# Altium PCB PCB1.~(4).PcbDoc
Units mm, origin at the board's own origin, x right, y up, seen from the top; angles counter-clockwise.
Board outline 152.4 x 101.6 mm, 2 copper layers (Top Layer, Bottom Layer); 2 components, 2 nets, 16 pads, 0 vias.
Unrouted connection lines stored in the file: 1.
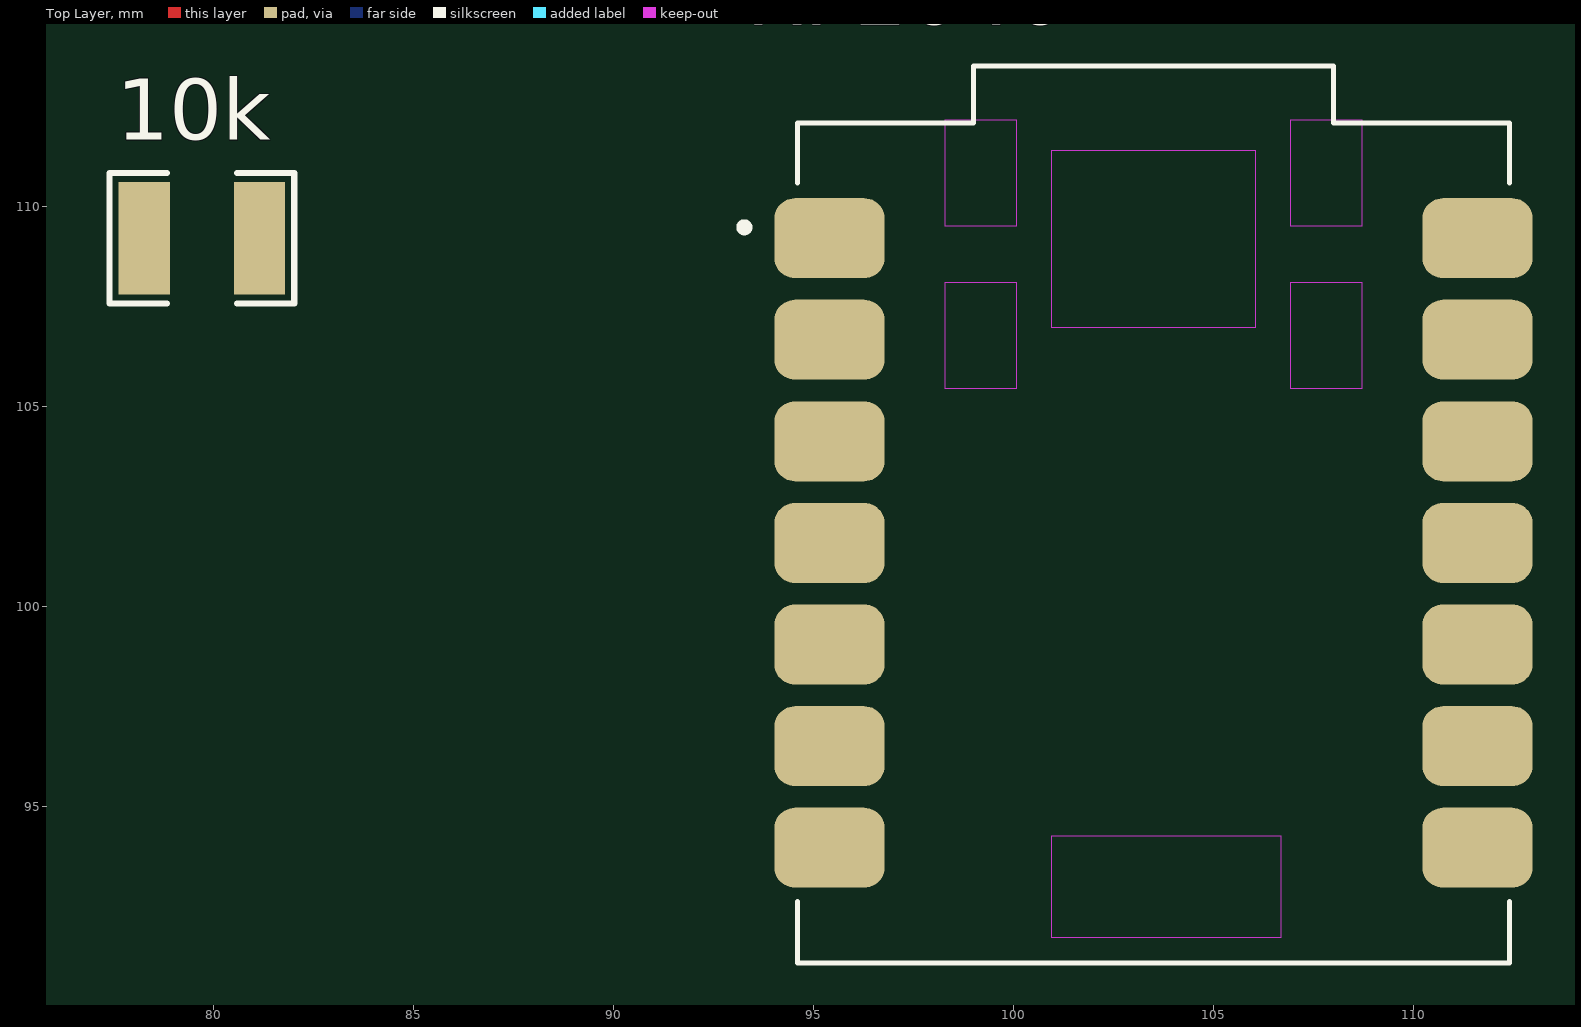
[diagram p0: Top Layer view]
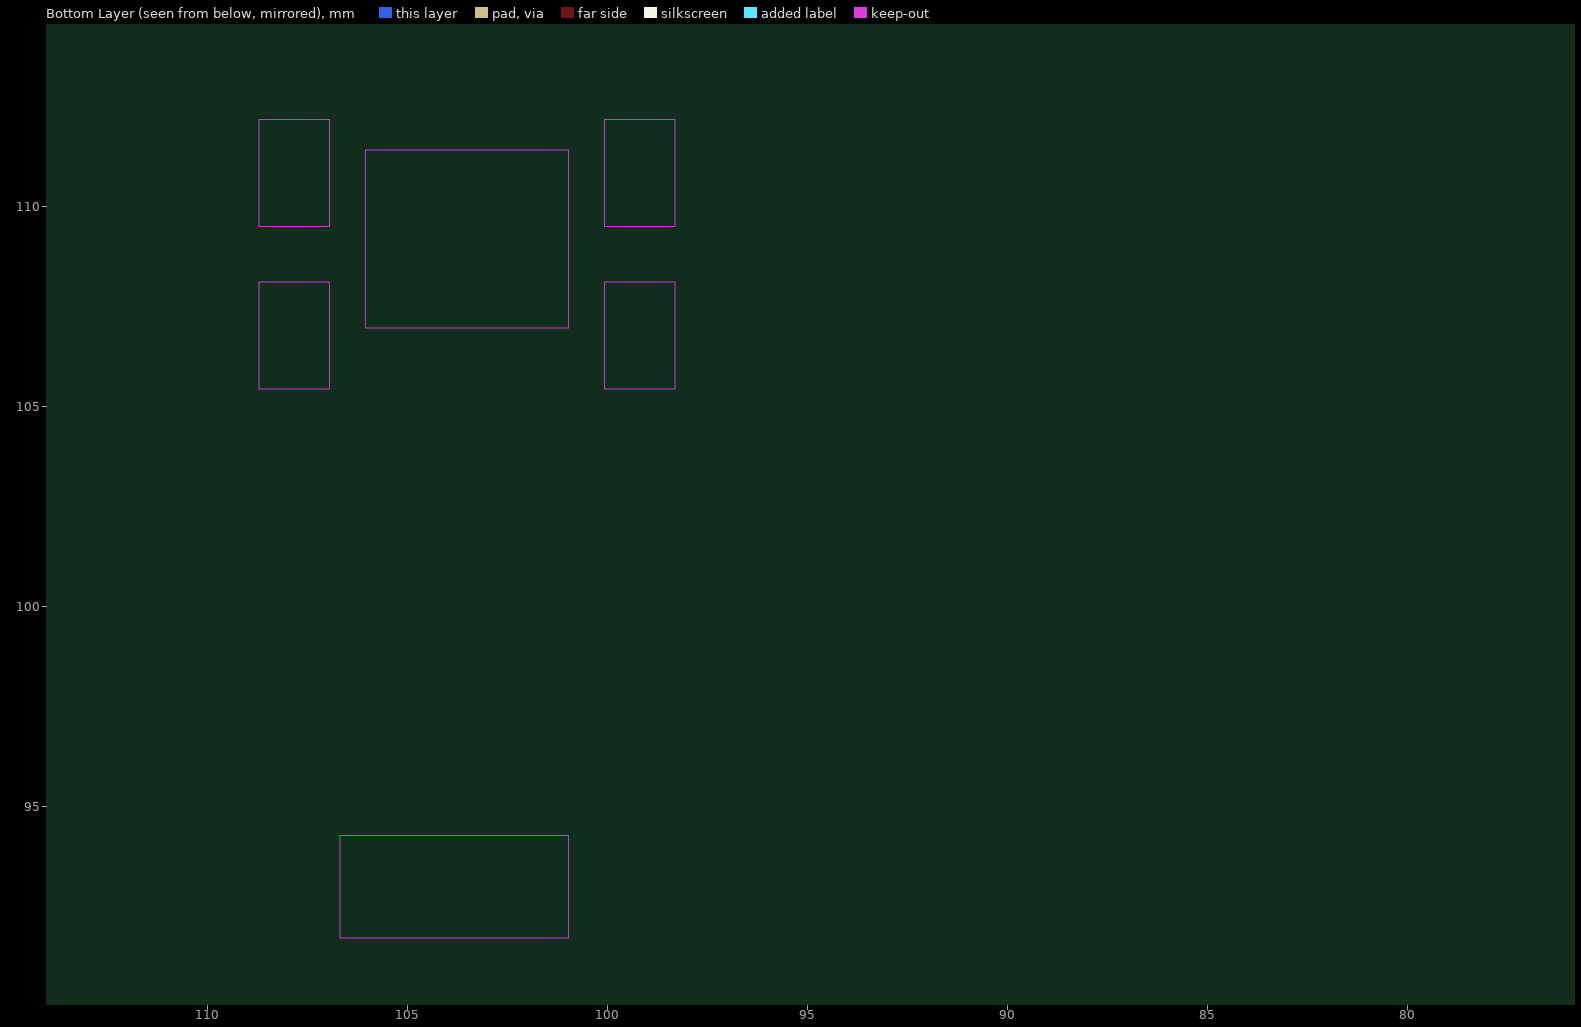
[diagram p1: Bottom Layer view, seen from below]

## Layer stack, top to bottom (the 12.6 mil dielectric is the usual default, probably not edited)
Top Solder: solder mask 0.0102, Solder Resist, Dk 3.5
Top Layer: signal copper 0.0356
Dielectric 1: dielectric 0.32, FR-4, Dk 4.8
Bottom Layer: signal copper 0.0356
Bottom Solder: solder mask 0.0102, Solder Resist, Dk 3.5

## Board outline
25.4,25.4 177.8,25.4 177.8,127 25.4,127

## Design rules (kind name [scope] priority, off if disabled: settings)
Clearance [All] p1: gap=0.254 ignorepadtopadclearanceinfootprint=FALSE except(0: Arc-Hole Track-Hole SMDPad-Hole THPad-Hole Via-Hole Fill-Hole Poly-Hole Region-Hole Text-Hole)
PolygonConnect [All] p1: connectstyle=Relief reliefconductorwidth=0.254 reliefentries=4 polygonreliefangle="90 Angle" airgapwidth=0.254
RoomDefinition XIAO_Schem [InComponentClass('XIAO_Schem')] p1: confinementstyle=ConfineIn formatcopy=TRUE lockcomponents=FALSE outline 92.837,90.678 113.411,90.678 113.411,116.586 92.837,116.586
RoutingVias [All] p1: holewidth=0.711 width=1.27 viastyle="Through Hole" minholewidth=0.711 minwidth=1.27 maxholewidth=0.711 maxwidth=1.27
SolderMaskExpansion [All] p1: expansion=0.102 istentingtop=FALSE
Width [All] p1: maxlimit=0.254 minlimit=0.254 preferedwidth=0.254
30 further rules are at their usual default settings.

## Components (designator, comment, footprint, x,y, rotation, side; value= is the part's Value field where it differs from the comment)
10k "10kΩ" 10k 79.712,109.22 r0 top
RP2040 "102010428" 102010428 103.505,101.6 r0 top

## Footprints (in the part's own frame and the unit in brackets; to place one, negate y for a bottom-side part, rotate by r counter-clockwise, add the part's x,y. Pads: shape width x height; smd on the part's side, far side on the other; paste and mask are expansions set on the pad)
10k [mm]
  rect 1.283x2.808 smd paste-100 mask+0.051: 1(-1.441,0) 2(1.441,0)
  silkscreen extent -2.31,-1.63 2.31,1.63, body extent -1.55,-0.76 1.55,0.84, height 0.55
102010428 [mm]
  rrect50% 2.75x2 smd: 1(-8.1,7.62) 2(-8.1,5.08) 3(-8.1,2.54) 4(-8.1,0) 5(-8.1,-2.54) 6(-8.1,-5.08) 7(-8.1,-7.62) 8(8.1,-7.62) 9(8.1,-5.08) 10(8.1,-2.54) 11(8.1,0) 12(8.1,2.54) 13(8.1,5.08) 14(8.1,7.62)
  Keep-Out Layer region: 3.175,-9.865 -2.54,-9.865 -2.54,-7.325 3.175,-7.325
  Keep-Out Layer region: -3.429,7.915 -5.207,7.915 -5.207,10.582 -3.429,10.582
  Keep-Out Layer region: -3.429,3.851 -5.207,3.851 -5.207,6.518 -3.429,6.518
  Keep-Out Layer region: 5.207,3.851 3.429,3.851 3.429,6.518 5.207,6.518
  Keep-Out Layer region: 5.207,7.915 3.429,7.915 3.429,10.582 5.207,10.582
  Keep-Out Layer region: 2.54,5.375 -2.54,5.375 -2.54,9.82 2.54,9.82
  silkscreen extent -10.33,-10.5 8.9,11.92, body extent -8.75,-10.5 8.75,11.5, height 4.41

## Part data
10k: library part 10k, JLCPCB Part Class="Extended Part", Manufacturer=Tyohm(幸亚电阻), Manufacturer Part=RMC120610K1%N
RP2040: "RP2040 XIAO RP2040 series ARMÂ® CortexÂ®-M0+ MCU 32-Bit Embedded Evaluation Board", Package=None

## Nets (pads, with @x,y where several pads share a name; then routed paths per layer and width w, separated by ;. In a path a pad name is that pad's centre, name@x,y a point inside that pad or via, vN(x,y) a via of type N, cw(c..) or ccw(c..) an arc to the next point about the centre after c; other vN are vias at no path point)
Net10k_2: 10k.2 RP2040.1
Net220Ω_2: RP2040.3
pads on no net: 10k.1 RP2040.2 RP2040.4 RP2040.5 RP2040.6 RP2040.7 RP2040.8 RP2040.9 RP2040.10 RP2040.11 RP2040.12 RP2040.13 RP2040.14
